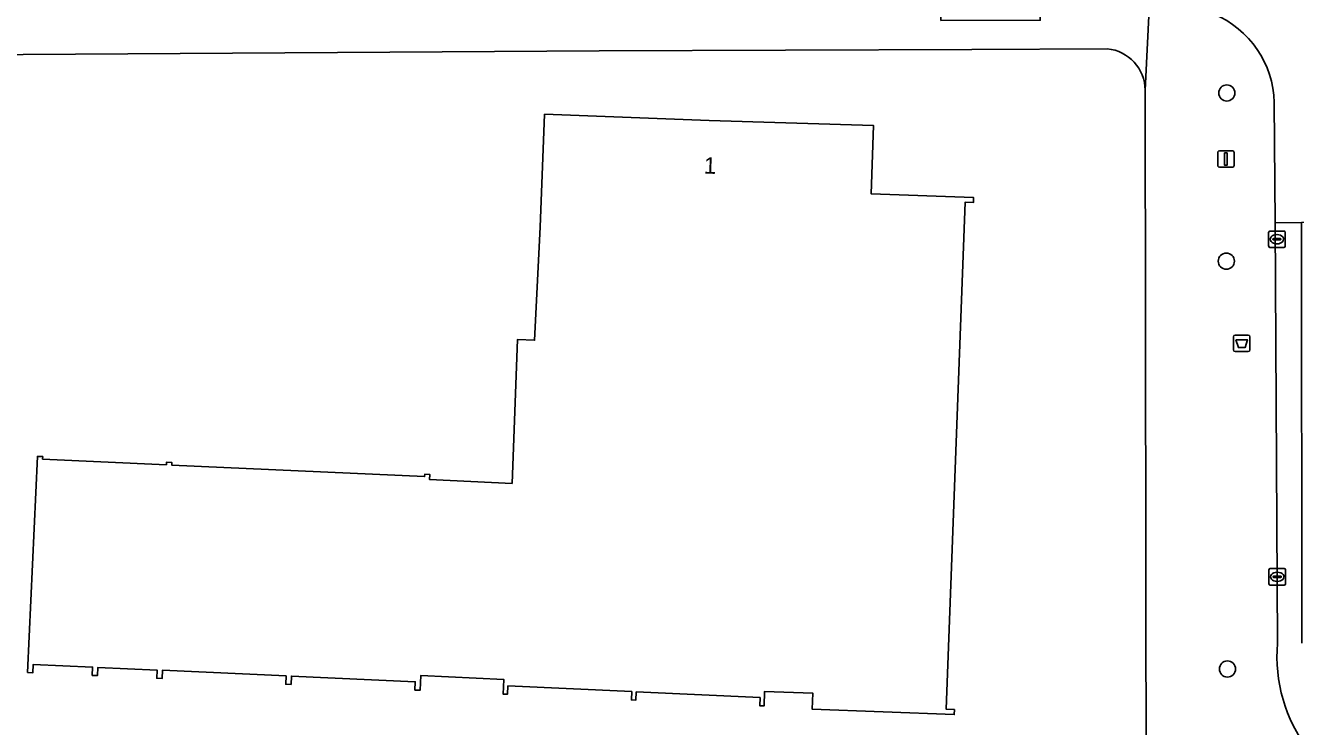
# Model space of a CAD drawing. Extents: x 160732 to 162107, y 387428 to 388479.
# Drawn here: x 161225.5 to 161302.4, y 387764 to 387806.4 of the extents above; entities that cross this region are included whole.
import ezdxf

# ---------------------------------------------------------------- set-up
doc = ezdxf.new("R2010")
doc.units = 0
for name, color, linetype in [('IMGEO_Afvalbak', 7, 'Continuous'), ('IMGEO_Boom', 7, 'Continuous'), ('IMGEO_Erf', 7, 'Continuous'), ('IMGEO_Kolk', 7, 'Continuous'), ('IMGEO_Lichtmast', 7, 'Continuous'), ('IMGEO_Pand', 7, 'Continuous'), ('IMGEO_Pand_nummerreeks', 7, 'Continuous'), ('IMGEO_Rijbaan_lokaal_gesloten', 7, 'Continuous'), ('IMGEO_Rijbaan_lokaal_open', 7, 'Continuous'), ('IMGEO_Voetpad_open', 7, 'Continuous')]:
    doc.layers.add(name, color=color, linetype=linetype)

msp = doc.modelspace()

# ---------------------------------------------------------------- linework, layer by layer
at = {"layer": 'IMGEO_Afvalbak'}
for p, q in [((161298.651, 387786.758), (161298.651, 387787.558)), ((161298.651, 387787.558), (161298.651, 387786.758)), ((161298.751, 387787.658), (161299.541, 387787.658)), ((161299.541, 387787.658), (161298.751, 387787.658)), ((161299.641, 387787.558), (161299.641, 387786.758)), ((161299.641, 387786.758), (161299.641, 387787.558)), ((161299.541, 387786.658), (161298.751, 387786.658)), ((161298.751, 387786.658), (161299.541, 387786.658))]:
    msp.add_line(p, q, dxfattribs=at)
msp.add_lwpolyline([(161298.794, 387787.372), (161299.498, 387787.372), (161299.349, 387786.902), (161298.943, 387786.902), (161298.794, 387787.372)], dxfattribs=at)
for centre, start, end in [((161298.751, 387787.558), 90, 180), ((161298.751, 387787.558), 90, 180), ((161299.541, 387787.558), 0, 90), ((161299.541, 387787.558), 360, 90), ((161298.751, 387786.758), 180, 270), ((161298.751, 387786.758), 180, 270), ((161299.541, 387786.758), 270, 0), ((161299.541, 387786.758), 270, 0)]:
    msp.add_arc(centre, 0.1, start, end, dxfattribs=at)
at = {"layer": 'IMGEO_Boom'}
for centre in [(161298.245, 387802.316), (161298.217, 387792.132), (161298.284, 387767.437)]:
    msp.add_circle(centre, 0.489, dxfattribs=at)
at = {"layer": 'IMGEO_Erf'}
for points in [[(161291.009, 387804.992), (161282.806, 387804.942), (161260.216, 387804.873), (161225.336, 387804.636)], [(161293.367, 387759.476), (161293.305, 387802.486)]]:
    msp.add_lwpolyline(points, dxfattribs=at)
msp.add_lwpolyline([(161249.658, 387779.234), (161249.967, 387779.22), (161249.953, 387778.91), (161254.95, 387778.68), (161255.274, 387787.383), (161256.312, 387787.344), (161256.66, 387794.184), (161256.915, 387801.027), (161266.881, 387800.656), (161276.849, 387800.338), (161276.695, 387796.21), (161282.903, 387795.979), (161282.891, 387795.68), (161282.393, 387795.699), (161281.25, 387765.002), (161281.749, 387764.983), (161281.737, 387764.683), (161273.138, 387765.004), (161273.174, 387765.971), (161270.25, 387766.08), (161270.218, 387765.201), (161269.948, 387765.213), (161269.97, 387765.712), (161262.473, 387766.055), (161262.45, 387765.555), (161262.18, 387765.568), (161262.202, 387766.067), (161254.695, 387766.41), (161254.671, 387765.91), (161254.401, 387765.922), (161254.442, 387766.811), (161249.423, 387767.04), (161249.382, 387766.15), (161249.062, 387766.163), (161249.084, 387766.663), (161241.587, 387767.005), (161241.563, 387766.505), (161241.243, 387766.519), (161241.265, 387767.018), (161233.768, 387767.361), (161233.745, 387766.861), (161233.425, 387766.875), (161233.447, 387767.374), (161229.858, 387767.538), (161229.835, 387767.037), (161229.515, 387767.051), (161229.537, 387767.55), (161225.948, 387767.714), (161225.925, 387767.214), (161225.604, 387767.227), (161226.202, 387780.311), (161226.521, 387780.297), (161226.514, 387780.147), (161234.01, 387779.803), (161234.016, 387779.952), (161234.345, 387779.936), (161234.338, 387779.786), (161249.652, 387779.085)], close=True, dxfattribs=at)
msp.add_arc((161290.729, 387802.431), 2.577, 1.2314, 83.7605, dxfattribs=at)
at = {"layer": 'IMGEO_Kolk'}
for p, q in [((161300.78, 387793.032), (161300.78, 387793.884)), ((161300.855, 387793.958), (161301.707, 387793.958)), ((161301.039, 387793.452), (161301.039, 387793.464)), ((161301.082, 387793.501), (161301.48, 387793.501)), ((161301.268, 387793.738), (161301.293, 387793.738)), ((161301.523, 387793.464), (161301.523, 387793.452)), ((161301.781, 387793.884), (161301.781, 387793.032)), ((161301.707, 387792.958), (161300.855, 387792.958)), ((161301.477, 387793.415), (161301.079, 387793.415)), ((161301.291, 387793.178), (161301.266, 387793.178)), ((161300.8, 387772.595), (161300.8, 387773.447)), ((161300.875, 387773.521), (161301.727, 387773.521)), ((161301.801, 387773.447), (161301.801, 387772.595)), ((161301.059, 387773.015), (161301.059, 387773.027)), ((161301.497, 387772.978), (161301.099, 387772.978)), ((161301.102, 387773.064), (161301.5, 387773.064)), ((161301.311, 387772.741), (161301.286, 387772.741)), ((161301.288, 387773.301), (161301.313, 387773.301)), ((161301.543, 387773.027), (161301.543, 387773.015)), ((161301.727, 387772.521), (161300.875, 387772.521))]:
    msp.add_line(p, q, dxfattribs=at)
for points in [[(161300.78, 387793.032), (161300.78, 387793.884)], [(161300.855, 387793.958), (161301.707, 387793.958)], [(161301.781, 387793.884), (161301.781, 387793.032)], [(161301.707, 387792.958), (161300.855, 387792.958)], [(161300.8, 387772.595), (161300.8, 387773.447)], [(161300.875, 387773.521), (161301.727, 387773.521)], [(161301.801, 387773.447), (161301.801, 387772.595)], [(161301.727, 387772.521), (161300.875, 387772.521)]]:
    msp.add_lwpolyline(points, dxfattribs=at)
for centre, radius, start, end in [((161300.857, 387793.882), 0.0765, 91.55205, 178.44795), ((161300.857, 387793.882), 0.0765, 91.55205, 178.44795), ((161301.079, 387793.461), 0.0403, 85.87752, 175.75265), ((161301.076, 387793.451), 0.0366, 178.93798, 274.71019), ((161301.48, 387793.458), 0.043, 264.86636, 352.45326), ((161301.484, 387793.463), 0.0386, 1.73085, 96.63898), ((161301.705, 387793.882), 0.0765, 1.55205, 88.44795), ((161301.705, 387793.882), 0.0765, 1.55205, 88.44795), ((161300.857, 387793.034), 0.0765, 181.55205, 268.44795), ((161300.857, 387793.034), 0.0765, 181.55205, 268.44795), ((161301.705, 387793.034), 0.0765, 271.55205, 358.44795), ((161301.705, 387793.034), 0.0765, 271.55205, 358.44795), ((161300.877, 387773.445), 0.0765, 91.55205, 178.44795), ((161300.877, 387773.445), 0.0765, 91.55205, 178.44795), ((161301.725, 387773.445), 0.0765, 1.55205, 88.44795), ((161301.725, 387773.445), 0.0765, 1.55205, 88.44795), ((161301.099, 387773.024), 0.0403, 85.87752, 175.75265), ((161301.096, 387773.014), 0.0366, 178.93798, 274.71019), ((161301.5, 387773.021), 0.043, 264.86636, 352.45326), ((161301.504, 387773.026), 0.0386, 1.73085, 96.63898), ((161300.877, 387772.597), 0.0765, 181.55205, 268.44795), ((161300.877, 387772.597), 0.0765, 181.55205, 268.44795), ((161301.725, 387772.597), 0.0765, 271.55205, 358.44795), ((161301.725, 387772.597), 0.0765, 271.55205, 358.44795)]:
    msp.add_arc(centre, radius, start, end, dxfattribs=at)
for centre, major_axis, ratio, start_param, end_param in [((161301.267, 387793.458), (-0.387, 0.002), 0.722429, 4.712389, 7.853982), ((161301.292, 387793.458), (-0.39, 0.002), 0.717154, 1.570796, 4.712389), ((161301.287, 387773.021), (-0.387, 0.002), 0.722429, 4.712389, 7.853982), ((161301.312, 387773.021), (-0.39, 0.002), 0.717154, 1.570796, 4.712389)]:
    msp.add_ellipse(centre, major_axis=major_axis, ratio=ratio, start_param=start_param, end_param=end_param, dxfattribs=at)
at = {"layer": 'IMGEO_Lichtmast'}
for p, q in [((161297.694, 387797.916), (161297.694, 387798.716)), ((161297.694, 387798.716), (161297.694, 387797.916)), ((161297.794, 387798.816), (161298.584, 387798.816)), ((161298.584, 387798.816), (161297.794, 387798.816)), ((161298.684, 387798.716), (161298.684, 387797.916)), ((161298.684, 387797.916), (161298.684, 387798.716)), ((161298.584, 387797.816), (161297.794, 387797.816)), ((161297.794, 387797.816), (161298.584, 387797.816))]:
    msp.add_line(p, q, dxfattribs=at)
msp.add_lwpolyline([(161298.114, 387798.691), (161298.264, 387798.691), (161298.264, 387797.941), (161298.114, 387797.941), (161298.114, 387798.691)], dxfattribs=at)
for centre, start, end in [((161297.794, 387798.716), 90, 180), ((161297.794, 387798.716), 90, 180), ((161298.584, 387798.716), 0, 90), ((161298.584, 387798.716), 360, 90), ((161297.794, 387797.916), 180, 270), ((161297.794, 387797.916), 180, 270), ((161298.584, 387797.916), 270, 0), ((161298.584, 387797.916), 270, 0)]:
    msp.add_arc(centre, 0.1, start, end, dxfattribs=at)
at = {"layer": 'IMGEO_Pand'}
msp.add_lwpolyline([(161249.953, 387778.91), (161249.967, 387779.22), (161249.658, 387779.234), (161249.652, 387779.085), (161234.338, 387779.786), (161234.345, 387779.936), (161234.016, 387779.952), (161234.01, 387779.803), (161226.514, 387780.147), (161226.521, 387780.297), (161226.202, 387780.311), (161225.604, 387767.227), (161225.925, 387767.214), (161225.948, 387767.714), (161229.537, 387767.55), (161229.515, 387767.051), (161229.835, 387767.037), (161229.858, 387767.538), (161233.447, 387767.374), (161233.425, 387766.875), (161233.745, 387766.861), (161233.768, 387767.361), (161241.265, 387767.018), (161241.243, 387766.519), (161241.563, 387766.505), (161241.587, 387767.005), (161249.084, 387766.663), (161249.062, 387766.163), (161249.382, 387766.15), (161249.423, 387767.04), (161254.442, 387766.811), (161254.401, 387765.922), (161254.671, 387765.91), (161254.695, 387766.41), (161262.202, 387766.067), (161262.18, 387765.568), (161262.45, 387765.555), (161262.473, 387766.055), (161269.97, 387765.712), (161269.948, 387765.213), (161270.218, 387765.201), (161270.25, 387766.08), (161273.174, 387765.971), (161273.138, 387765.004), (161281.737, 387764.683), (161281.749, 387764.983), (161281.25, 387765.002), (161282.393, 387795.699), (161282.891, 387795.68), (161282.903, 387795.979), (161276.695, 387796.21), (161276.849, 387800.338), (161266.881, 387800.656), (161256.915, 387801.027), (161256.66, 387794.184), (161256.312, 387787.344), (161255.274, 387787.383), (161254.95, 387778.68)], close=True, dxfattribs=at)
at = {"layer": 'IMGEO_Rijbaan_lokaal_gesloten'}
msp.add_lwpolyline([(161302.799, 387769.011), (161302.774, 387794.477), (161301.166, 387794.444), (161301.317, 387769.01)], dxfattribs=at)
msp.add_arc((161310.679, 387768.21), 9.396, 175.11431, 258.1471, dxfattribs=at)
at = {"layer": 'IMGEO_Rijbaan_lokaal_open'}
msp.add_lwpolyline([(161301.123, 387801.736), (161301.166, 387794.444), (161302.774, 387794.477), (161306.309, 387794.549), (161307.76, 387794.57), (161307.735, 387796.726), (161306.309, 387796.724), (161306.291, 387818.834)], dxfattribs=at)
msp.add_arc((161295.165, 387801.592), 5.96, 1.38425, 67.37183, dxfattribs=at)
at = {"layer": 'IMGEO_Voetpad_open'}
for points in [[(161244.672, 387807.689), (161224.483, 387807.637), (161221.503, 387807.631), (161221.513, 387806.529), (161214.577, 387806.511), (161214.578, 387807.602), (161200.286, 387807.545), (161196.815, 387807.535), (161187.735, 387807.527), (161187.737, 387806.409), (161174.383, 387806.378), (161174.376, 387807.484), (161166.936, 387807.485), (161166.859, 387804.507), (161210.227, 387804.485), (161215.499, 387804.51), (161220.629, 387804.612), (161222.311, 387804.607), (161222.607, 387804.606), (161225.336, 387804.636), (161260.216, 387804.873), (161282.806, 387804.942), (161291.009, 387804.992)], [(161293.305, 387802.486), (161293.564, 387807.793), (161292.574, 387807.805), (161286.933, 387807.801), (161286.943, 387806.714), (161280.924, 387806.708), (161280.924, 387807.785)], [(161293.564, 387807.793), (161293.305, 387802.486), (161293.367, 387759.476), (161308.749, 387759.014)], [(161301.317, 387769.01), (161301.166, 387794.444), (161301.123, 387801.736)]]:
    msp.add_lwpolyline(points, dxfattribs=at)
for centre, radius, start, end in [((161295.165, 387801.592), 5.96, 1.38425, 67.37183), ((161290.729, 387802.431), 2.577, 1.2314, 83.7605), ((161310.679, 387768.21), 9.396, 175.11431, 258.1471)]:
    msp.add_arc(centre, radius, start, end, dxfattribs=at)

# ---------------------------------------------------------------- texts
at = {"layer": 'IMGEO_Pand_nummerreeks'}
msp.add_text('1', height=1, rotation=357.86652, dxfattribs=at).set_placement((161266.553, 387797.44))

doc.saveas('drawing.dxf')
